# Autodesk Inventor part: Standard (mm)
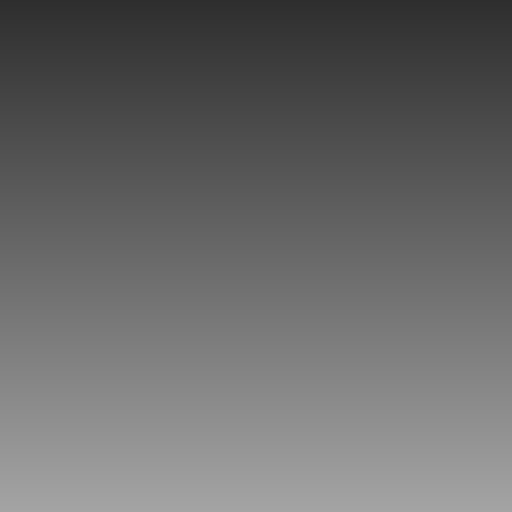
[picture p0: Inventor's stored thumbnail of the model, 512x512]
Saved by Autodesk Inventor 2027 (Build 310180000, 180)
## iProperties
Shininess: 64.0
Length Units: 11269
Angle Units: 11279
Time Units: 11290
Mass Units: 11283
Length Display Precision: 3
Angle Display Precision: 2
Compacted: True
Part Number: Standard (mm)
Document SubType Name: Modeling
Created: 2002-07
Density: 1 g/cm^3
Material: Generic
Appearance: Default
Density: 0.0
Volumn: 0.0
Area: 0.0
PropertySet Name: Model Information
Control State: 0
Master: False
Checked Out: False
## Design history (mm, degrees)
